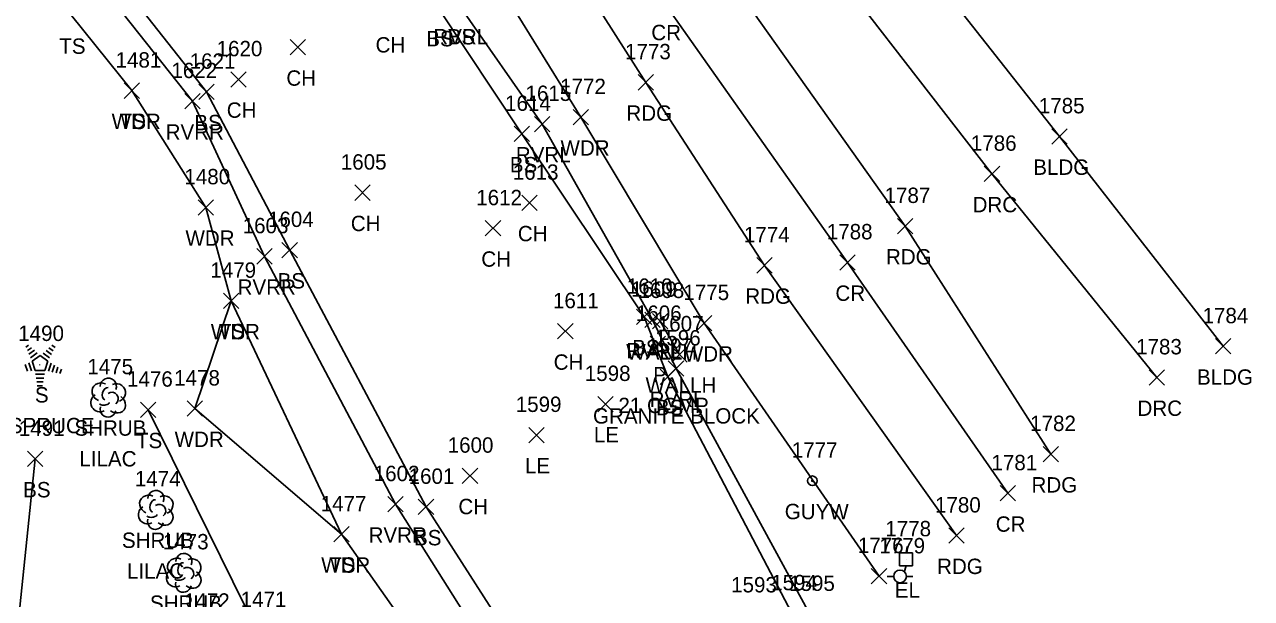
# Model space of a CAD drawing. Extents: x 1653908 to 1654393, y 539913 to 544256.
# Drawn here: x 1654097.1 to 1654256.7, y 541473.4 to 541548 of the extents above; entities that cross this region are included whole.
import ezdxf

# ---------------------------------------------------------------- set-up
doc = ezdxf.new("R2010")
doc.units = 0
for name, color, linetype in [('D_A', 7, 'Continuous'), ('D_C', 7, 'Continuous'), ('D_I', 7, 'Continuous'), ('D_TIC', 7, 'Continuous'), ('DHW', 7, 'Continuous'), ('L_A', 7, 'Continuous'), ('L_C', 7, 'Continuous'), ('L_I', 7, 'Continuous'), ('L_TIC', 7, 'Continuous'), ('LAWA', 7, 'Continuous'), ('LAWE', 7, 'Continuous'), ('LBC', 7, 'Continuous'), ('LELB', 7, 'Continuous'), ('LSH', 7, 'Continuous'), ('LTC', 7, 'Continuous'), ('P_A', 7, 'Continuous'), ('P_I', 7, 'Continuous'), ('P_TIC', 7, 'Continuous'), ('PEU', 7, 'Continuous'), ('PRC', 7, 'Continuous'), ('R_A', 7, 'Continuous'), ('R_I', 7, 'Continuous'), ('R_TIC', 7, 'Continuous'), ('RDP', 7, 'Continuous'), ('U_A', 7, 'Continuous'), ('U_I', 7, 'Continuous'), ('UEPT', 7, 'Continuous'), ('UP', 7, 'Continuous'), ('UPGW', 7, 'Continuous')]:
    doc.layers.add(name, color=color, linetype=linetype)

msp = doc.modelspace()

# ---------------------------------------------------------------- linework, layer by layer
at = {"layer": 'D_TIC'}
for points in [[(1654178.8, 541508.46), (1654180.8, 541510.46)], [(1654180.8, 541508.46), (1654178.8, 541510.46)], [(1654178.51, 541505.49), (1654180.51, 541507.49)], [(1654180.51, 541505.49), (1654178.51, 541507.49)], [(1654181.31, 541504.13), (1654183.31, 541506.13)], [(1654183.31, 541504.13), (1654181.31, 541506.13)]]:
    msp.add_lwpolyline(points, dxfattribs=at)
at = {"layer": 'DHW'}
msp.add_lwpolyline([(1654182.31, 541505.13), (1654179.8, 541509.46)], dxfattribs=at)
at = {"layer": 'L_TIC'}
for points in [[(1654131.7, 541544.07), (1654133.7, 541546.07)], [(1654133.7, 541544.07), (1654131.7, 541546.07)], [(1654123.95, 541539.9), (1654125.95, 541541.9)], [(1654125.95, 541539.9), (1654123.95, 541541.9)], [(1654110.1, 541538.43), (1654112.1, 541540.43)], [(1654112.1, 541538.43), (1654110.1, 541540.43)], [(1654110.1, 541538.43), (1654112.1, 541540.43)], [(1654112.1, 541538.43), (1654110.1, 541540.43)], [(1654119.79, 541538.28), (1654121.79, 541540.28)], [(1654121.79, 541538.28), (1654119.79, 541540.28)], [(1654117.98, 541537.06), (1654119.98, 541539.06)], [(1654119.98, 541537.06), (1654117.98, 541539.06)], [(1654163.46, 541534.09), (1654165.46, 541536.09)], [(1654165.46, 541534.09), (1654163.46, 541536.09)], [(1654168.48, 541534.98), (1654170.48, 541536.98)], [(1654170.48, 541534.98), (1654168.48, 541536.98)], [(1654160.8, 541532.8), (1654162.8, 541534.8)], [(1654162.8, 541532.8), (1654160.8, 541534.8)], [(1654230.73, 541532.48), (1654232.73, 541534.48)], [(1654232.73, 541532.48), (1654230.73, 541534.48)], [(1654140.09, 541525.16), (1654142.09, 541527.16)], [(1654142.09, 541525.16), (1654140.09, 541527.16)], [(1654119.71, 541523.25), (1654121.71, 541525.25)], [(1654121.71, 541523.25), (1654119.71, 541525.25)], [(1654161.8, 541523.84), (1654163.8, 541525.84)], [(1654163.8, 541523.84), (1654161.8, 541525.84)], [(1654157.06, 541520.53), (1654159.06, 541522.53)], [(1654159.06, 541520.53), (1654157.06, 541522.53)], [(1654130.62, 541517.7), (1654132.62, 541519.7)], [(1654132.62, 541517.7), (1654130.62, 541519.7)], [(1654127.33, 541516.88), (1654129.33, 541518.88)], [(1654129.33, 541516.88), (1654127.33, 541518.88)], [(1654123, 541511.09), (1654125, 541513.09)], [(1654125, 541511.09), (1654123, 541513.09)], [(1654123, 541511.09), (1654125, 541513.09)], [(1654125, 541511.09), (1654123, 541513.09)], [(1654176.72, 541509.01), (1654178.72, 541511.01)], [(1654178.72, 541509.01), (1654176.72, 541511.01)], [(1654177.82, 541508.62), (1654179.82, 541510.62)], [(1654179.82, 541508.62), (1654177.82, 541510.62)], [(1654184.51, 541508.19), (1654186.51, 541510.19)], [(1654186.51, 541508.19), (1654184.51, 541510.19)], [(1654166.47, 541507.13), (1654168.47, 541509.13)], [(1654168.47, 541507.13), (1654166.47, 541509.13)], [(1654252.02, 541505.18), (1654254.02, 541507.18)], [(1654254.02, 541505.18), (1654252.02, 541507.18)], [(1654180.86, 541502.28), (1654182.86, 541504.28)], [(1654182.86, 541502.28), (1654180.86, 541504.28)], [(1654179.81, 541501.22), (1654181.81, 541503.22)], [(1654181.81, 541501.22), (1654179.81, 541503.22)], [(1654112.22, 541496.93), (1654114.22, 541498.93)], [(1654114.22, 541496.93), (1654112.22, 541498.93)], [(1654118.3, 541497.08), (1654120.3, 541499.08)], [(1654120.3, 541497.08), (1654118.3, 541499.08)], [(1654171.69, 541497.67), (1654173.69, 541499.67)], [(1654173.69, 541497.67), (1654171.69, 541499.67)], [(1654162.72, 541493.64), (1654164.72, 541495.64)], [(1654164.72, 541493.64), (1654162.72, 541495.64)], [(1654097.52, 541490.53), (1654099.52, 541492.53)], [(1654099.52, 541490.53), (1654097.52, 541492.53)], [(1654154.07, 541488.34), (1654156.07, 541490.34)], [(1654156.07, 541488.34), (1654154.07, 541490.34)], [(1654144.37, 541484.64), (1654146.37, 541486.64)], [(1654146.37, 541484.64), (1654144.37, 541486.64)], [(1654148.35, 541484.29), (1654150.35, 541486.29)], [(1654150.35, 541484.29), (1654148.35, 541486.29)], [(1654137.36, 541480.73), (1654139.36, 541482.73)], [(1654139.36, 541480.73), (1654137.36, 541482.73)], [(1654137.36, 541480.73), (1654139.36, 541482.73)], [(1654139.36, 541480.73), (1654137.36, 541482.73)], [(1654207.26, 541475.29), (1654209.26, 541477.29)], [(1654209.26, 541475.29), (1654207.26, 541477.29)]]:
    msp.add_lwpolyline(points, dxfattribs=at)
at = {"layer": 'LAWA'}
for points in [[(1654127.87, 541598.37), (1654149.12, 541568.97), (1654169.48, 541535.98), (1654185.51, 541509.19), (1654208.26, 541476.29)], [(1654160.84, 541449.79), (1654138.36, 541481.73), (1654119.3, 541498.08), (1654124, 541512.09), (1654120.71, 541524.25), (1654111.1, 541539.43)]]:
    msp.add_lwpolyline(points, dxfattribs=at)
at = {"layer": 'LAWE'}
for points in [[(1654199.26, 541471.36), (1654181.86, 541503.28), (1654178.82, 541509.62), (1654164.46, 541535.09), (1654153.73, 541550.44), (1654126.86, 541584.5), (1654110.11, 541605.8), (1654090.45, 541629.39), (1654082.44, 541647.34), (1654069.57, 541661.67), (1654051.08, 541684.15), (1654038.47, 541696.15), (1654026.73, 541704.45), (1654010.8, 541724.45), (1653979.68, 541745.5), (1653961.84, 541751.35), (1653943.48, 541769.15)], [(1654165.75, 541453.3), (1654145.37, 541485.64), (1654128.33, 541517.88), (1654118.98, 541538.06), (1654102.88, 541558.43), (1654087.64, 541571.29), (1654080.69, 541574.23), (1654068.7, 541590.65), (1654047.98, 541616.51), (1654043.58, 541623.07), (1654031.27, 541642.94), (1654001.65, 541675.05), (1653981.82, 541702.27), (1653972.91, 541712.11), (1653946.21, 541722.65), (1653929.33, 541730.47)]]:
    msp.add_lwpolyline(points, dxfattribs=at)
at = {"layer": 'LBC'}
msp.add_lwpolyline([(1654253.02, 541506.18), (1654231.73, 541533.48), (1654203.1, 541569.78), (1654212.42, 541577.2)], dxfattribs=at)
at = {"layer": 'LELB'}
for points in [[(1654196.93, 541471.45), (1654180.81, 541502.22), (1654177.72, 541510.01), (1654161.8, 541533.8), (1654150.94, 541550.19), (1654125.25, 541583.39), (1654108.34, 541603.18), (1654088.22, 541626.26), (1654081.33, 541637.75)], [(1654167.93, 541456.34), (1654149.35, 541485.29), (1654131.62, 541518.7), (1654120.79, 541539.28), (1654104.43, 541560.1), (1654087.96, 541576.78)], [(1654111.1, 541539.43), (1654103.25, 541549.22), (1654091.64, 541558.03), (1654091.64, 541546.03), (1654092.66, 541531.19), (1654087.6, 541525.06), (1654080.77, 541525.51), (1654079.92, 541532.39), (1654080.83, 541544.02)], [(1654138.36, 541481.73), (1654124, 541512.09)], [(1654160.84, 541449.79), (1654142.77, 541456.54), (1654127.36, 541469.26), (1654113.22, 541497.93)], [(1654131.27, 541408.59), (1654106.78, 541414.13), (1654086.76, 541412.9), (1654094.61, 541453.8), (1654098.52, 541491.53)]]:
    msp.add_lwpolyline(points, dxfattribs=at)
at = {"layer": 'LSH'}
for p, q in [((1654108, 541499.55), (1654108, 541499.55)), ((1654108, 541499.55), (1654108, 541499.55)), ((1654114.18, 541484.96), (1654114.18, 541484.96)), ((1654114.18, 541484.96), (1654114.18, 541484.96)), ((1654117.82, 541476.77), (1654117.82, 541476.77)), ((1654117.82, 541476.77), (1654117.82, 541476.77))]:
    msp.add_line(p, q, dxfattribs=at)
for centre in [(1654108.04, 541500.99), (1654114.23, 541486.39), (1654117.87, 541478.2)]:
    msp.add_arc(centre, 1.05, 335.5272, 180.9563, dxfattribs=at)
for centre, major_axis, ratio, start_param, end_param in [((1654107.21, 541500.22), (1.21, -0.51), 0.895232, 1.570796, 4.712389), ((1654107.79, 541500.01), (-0.208, -0.792), 0.645439, 3.141593, 6.283185), ((1654109.04, 541500.13), (-1.14, -0.48), 0.949671, 1.570796, 4.712389), ((1654106.91, 541498.84), (0.58, -1.04), 0.959034, 3.141593, 6.283185), ((1654107.54, 541498.8), (-0.625, -0.083), 0.423636, 0, 3.141593), ((1654108.5, 541499.38), (-0.5, 0.667), 0.989748, 3.141593, 6.283185), ((1654109, 541498.72), (-1.09, 0.79), 0.841452, 1.570796, 4.712389), ((1654108, 541498.05), (0.26, 1.06), 0.942809, 1.570796, 4.712389), ((1654113.39, 541485.62), (1.21, -0.51), 0.895232, 1.570796, 4.712389), ((1654113.98, 541485.42), (-0.208, -0.792), 0.645439, 3.141593, 6.283185), ((1654115.23, 541485.54), (-1.14, -0.48), 0.949671, 1.570796, 4.712389), ((1654113.1, 541484.25), (0.58, -1.04), 0.959034, 3.141593, 6.283185), ((1654114.68, 541484.79), (-0.5, 0.667), 0.989748, 3.141593, 6.283185), ((1654115.18, 541484.12), (-1.09, 0.79), 0.841452, 1.570796, 4.712389), ((1654114.18, 541483.46), (0.26, 1.06), 0.942809, 1.570796, 4.712389), ((1654113.73, 541484.21), (-0.625, -0.083), 0.423636, 0, 3.141593), ((1654117.03, 541477.43), (1.21, -0.51), 0.895232, 1.570796, 4.712389), ((1654117.61, 541477.22), (-0.208, -0.792), 0.645439, 3.141593, 6.283185), ((1654118.86, 541477.35), (-1.14, -0.48), 0.949671, 1.570796, 4.712389), ((1654116.74, 541476.06), (0.58, -1.04), 0.959034, 3.141593, 6.283185), ((1654118.32, 541476.6), (-0.5, 0.667), 0.989748, 3.141593, 6.283185), ((1654118.82, 541475.93), (-1.09, 0.79), 0.841452, 1.570796, 4.712389), ((1654117.82, 541475.27), (0.26, 1.06), 0.942809, 1.570796, 4.712389), ((1654117.36, 541476.02), (-0.625, -0.083), 0.423636, 0, 3.141593)]:
    msp.add_ellipse(centre, major_axis=major_axis, ratio=ratio, start_param=start_param, end_param=end_param, dxfattribs=at)
at = {"layer": 'LTC'}
for p, q in [((1654097.3, 541506.08), (1654097.65, 541506.34)), ((1654097.51, 541505.62), (1654098.04, 541506)), ((1654097.72, 541505.15), (1654098.42, 541505.66)), ((1654097.93, 541504.69), (1654098.8, 541505.32)), ((1654099.58, 541505.28), (1654100.39, 541504.69)), ((1654099.95, 541505.63), (1654100.63, 541505.13)), ((1654100.32, 541505.97), (1654100.87, 541505.58)), ((1654100.69, 541506.32), (1654101.11, 541506.02)), ((1654097.24, 541503.8), (1654097.51, 541502.96)), ((1654097.7, 541504.01), (1654098.03, 541502.99)), ((1654098.15, 541504.23), (1654099.16, 541504.97)), ((1654098.15, 541504.23), (1654098.54, 541503.04)), ((1654099.16, 541504.97), (1654100.16, 541504.24)), ((1654100.16, 541504.24), (1654099.77, 541503.04)), ((1654100.6, 541503.97), (1654100.26, 541502.93)), ((1654101.04, 541503.72), (1654100.75, 541502.83)), ((1654099.77, 541503.04), (1654098.54, 541503.04)), ((1654099.73, 541502.54), (1654098.58, 541502.54)), ((1654099.65, 541502.04), (1654098.66, 541502.04)), ((1654101.49, 541503.47), (1654101.25, 541502.74)), ((1654101.93, 541503.22), (1654101.74, 541502.64)), ((1654099.56, 541501.54), (1654098.73, 541501.54)), ((1654099.48, 541501.04), (1654098.8, 541501.04))]:
    msp.add_line(p, q, dxfattribs=at)
at = {"layer": 'P_TIC'}
for points in [[(1654176.92, 541539.51), (1654178.92, 541541.51)], [(1654178.92, 541539.51), (1654176.92, 541541.51)], [(1654210.67, 541520.82), (1654212.67, 541522.82)], [(1654212.67, 541520.82), (1654210.67, 541522.82)], [(1654203.16, 541516.09), (1654205.16, 541518.09)], [(1654205.16, 541516.09), (1654203.16, 541518.09)], [(1654192.38, 541515.71), (1654194.38, 541517.71)], [(1654194.38, 541515.71), (1654192.38, 541517.71)], [(1654229.6, 541491.16), (1654231.6, 541493.16)], [(1654231.6, 541491.16), (1654229.6, 541493.16)], [(1654224.01, 541486.06), (1654226.01, 541488.06)], [(1654226.01, 541486.06), (1654224.01, 541488.06)], [(1654217.32, 541480.56), (1654219.32, 541482.56)], [(1654219.32, 541480.56), (1654217.32, 541482.56)]]:
    msp.add_lwpolyline(points, dxfattribs=at)
at = {"layer": 'PEU'}
for points in [[(1654230.6, 541492.16), (1654211.67, 541521.82), (1654186.95, 541556.68), (1654161.81, 541592.26), (1654146.11, 541619.61), (1654138.24, 541633.78), (1654124.52, 541663.98), (1654122.03, 541667.7)], [(1654099.96, 541660.14), (1654114.2, 541641.31), (1654138.77, 541602.77), (1654156.2, 541574.57), (1654177.92, 541540.51), (1654193.38, 541516.71), (1654218.32, 541481.56)]]:
    msp.add_lwpolyline(points, dxfattribs=at)
at = {"layer": 'PRC'}
msp.add_lwpolyline([(1654225.01, 541487.06), (1654204.16, 541517.09), (1654180.22, 541550.99), (1654156.18, 541588.24), (1654139.45, 541615.76), (1654117.3, 541653.68), (1654111.9, 541663.59), (1654098.63, 541686.77), (1654084.43, 541705.04)], dxfattribs=at)
at = {"layer": 'R_TIC'}
for points in [[(1654221.95, 541527.61), (1654223.95, 541529.61)], [(1654223.95, 541527.61), (1654221.95, 541529.61)], [(1654243.38, 541501.13), (1654245.38, 541503.13)], [(1654245.38, 541501.13), (1654243.38, 541503.13)]]:
    msp.add_lwpolyline(points, dxfattribs=at)
at = {"layer": 'RDP'}
msp.add_lwpolyline([(1654244.38, 541502.13), (1654222.95, 541528.61), (1654195.82, 541563.61), (1654203.1, 541569.78)], dxfattribs=at)
at = {"layer": 'UEPT'}
for p, q in [((1654211.94, 541480.14), (1654211.77, 541479.31)), ((1654210.94, 541477.64), (1654210.94, 541479.31)), ((1654210.94, 541479.31), (1654212.61, 541479.31)), ((1654211.77, 541478.47), (1654211.77, 541478.47)), ((1654212.61, 541479.31), (1654212.61, 541477.64)), ((1654212.61, 541477.64), (1654210.94, 541477.64)), ((1654211.52, 541476.81), (1654211.77, 541477.64))]:
    msp.add_line(p, q, dxfattribs=at)
at = {"layer": 'UP'}
for p, q in [((1654209.34, 541476.24), (1654210.17, 541476.24)), ((1654211, 541476.25), (1654211, 541476.25)), ((1654212.67, 541476.25), (1654211.83, 541476.25)), ((1654211.83, 541476.25), (1654211.83, 541476.25)), ((1654212.67, 541476.25), (1654212.67, 541476.25))]:
    msp.add_line(p, q, dxfattribs=at)
msp.add_circle((1654211, 541476.25), 0.833, dxfattribs=at)
at = {"layer": 'UPGW'}
for radius in [0.625, 0.0833]:
    msp.add_circle((1654199.6, 541488.69), radius, dxfattribs=at)

# ---------------------------------------------------------------- texts
at = {"layer": 'D_A'}
for s, p in [('WALLH', (1654175.39, 541504.46)), ('WALLH', (1654177.9, 541500.13)), ('P', (1654178.89, 541501.49))]:
    msp.add_text(s, height=2, dxfattribs=at).set_placement(p)
at = {"layer": 'D_C'}
for s, p in [('21 CGMP', (1654174.37, 541497.49)), ('GRANITE BLOCK', (1654171.07, 541496.13))]:
    msp.add_text(s, height=2, dxfattribs=at).set_placement(p)
at = {"layer": 'D_I'}
for s, p in [('1608', (1654176.98, 541512.46)), ('1606', (1654176.64, 541509.49)), ('1607', (1654179.49, 541508.13))]:
    msp.add_text(s, height=2, dxfattribs=at).set_placement(p)
at = {"layer": 'L_A'}
for s, p in [('BS', (1654149.38, 541545.19)), ('RVRL', (1654150.3, 541545.44)), ('BS', (1654152.17, 541545.44)), ('TS', (1654101.66, 541544.22)), ('CH', (1654142.79, 541544.39)), ('CH', (1654131.19, 541540.07)), ('CH', (1654123.44, 541535.9)), ('WDR', (1654108.47, 541534.43)), ('TS', (1654109.51, 541534.43)), ('BS', (1654119.23, 541534.28)), ('RVRR', (1654115.49, 541533.06)), ('WDR', (1654166.84, 541530.98)), ('BS', (1654160.25, 541528.8)), ('RVRL', (1654161.03, 541530.09)), ('BLDG', (1654228.32, 541528.48)), ('CH', (1654139.57, 541521.16)), ('WDR', (1654118.07, 541519.25)), ('CH', (1654161.29, 541519.84)), ('CH', (1654156.54, 541516.53)), ('RVRR', (1654124.85, 541512.88)), ('BS', (1654130.06, 541513.7)), ('WDR', (1654121.36, 541507.09)), ('TS', (1654122.41, 541507.09)), ('BS', (1654176.16, 541505.01)), ('CH', (1654165.95, 541503.13)), ('RVRL', (1654175.39, 541504.62)), ('WDR', (1654182.88, 541504.19)), ('BLDG', (1654249.61, 541501.18)), ('S', (1654098.49, 541498.87)), ('RVRL', (1654178.43, 541498.28)), ('BS', (1654179.25, 541497.22)), ('SHRUB', (1654103.63, 541494.55)), ('LE', (1654171.18, 541493.67)), ('TS', (1654111.63, 541492.93)), ('WDR', (1654116.66, 541493.08)), ('LE', (1654162.21, 541489.64)), ('BS', (1654096.96, 541486.53)), ('CH', (1654153.56, 541484.34)), ('SHRUB', (1654109.81, 541479.96)), ('RVRR', (1654141.88, 541480.64)), ('BS', (1654147.79, 541480.29)), ('WDR', (1654135.72, 541476.73)), ('TS', (1654136.76, 541476.73)), ('SHRUB', (1654113.45, 541471.77))]:
    msp.add_text(s, height=2, dxfattribs=at).set_placement(p)
at = {"layer": 'L_C'}
for s, p in [('S. SPRUCE', (1654091.83, 541494.87)), ('LILAC', (1654104.27, 541490.55)), ('LILAC', (1654110.46, 541475.96))]:
    msp.add_text(s, height=2, dxfattribs=at).set_placement(p)
at = {"layer": 'L_I'}
for s, p in [('1620', (1654122.12, 541543.9)), ('1481', (1654108.98, 541542.43)), ('1481', (1654108.98, 541542.43)), ('1621', (1654118.62, 541542.28)), ('1622', (1654116.24, 541541.06)), ('1772', (1654166.79, 541538.98)), ('1614', (1654159.63, 541536.8)), ('1615', (1654162.29, 541538.09)), ('1785', (1654229.04, 541536.48)), ('1605', (1654138.27, 541529.16)), ('1480', (1654117.93, 541527.25)), ('1613', (1654160.63, 541527.84)), ('1612', (1654155.88, 541524.53)), ('1603', (1654125.51, 541520.88)), ('1604', (1654128.8, 541521.7)), ('1479', (1654121.3, 541515.09)), ('1479', (1654121.3, 541515.09)), ('1610', (1654175.46, 541513.01)), ('1611', (1654165.86, 541511.13)), ('1609', (1654176, 541512.62)), ('1775', (1654182.82, 541512.19)), ('1784', (1654250.33, 541509.18)), ('1490', (1654096.32, 541506.87)), ('1597', (1654178.12, 541505.22)), ('1596', (1654179.12, 541506.28)), ('1475', (1654105.31, 541502.55)), ('1598', (1654170, 541501.67)), ('1476', (1654110.47, 541500.93)), ('1478', (1654116.6, 541501.08)), ('1599', (1654161.02, 541497.64)), ('1491', (1654096.39, 541494.53)), ('1600', (1654152.17, 541492.34)), ('1474', (1654111.49, 541487.96)), ('1602', (1654142.55, 541488.64)), ('1601', (1654147.09, 541488.29)), ('1477', (1654135.66, 541484.73)), ('1477', (1654135.66, 541484.73)), ('1473', (1654115.13, 541479.77)), ('1776', (1654205.51, 541479.29)), ('1594', (1654194.24, 541474.45)), ('1593', (1654189.03, 541474.17)), ('1595', (1654196.57, 541474.36)), ('1472', (1654117.87, 541472.05)), ('1471', (1654125.24, 541472.26))]:
    msp.add_text(s, height=2, dxfattribs=at).set_placement(p)
at = {"layer": 'LTC'}
msp.add_text('.', height=1.04, rotation=270, dxfattribs=at).set_placement((1654099.04, 541503.98))
at = {"layer": 'P_A'}
for s, p in [('CR', (1654178.65, 541545.99)), ('RDG', (1654175.41, 541535.51)), ('RDG', (1654209.16, 541516.82)), ('RDG', (1654190.87, 541511.71)), ('CR', (1654202.59, 541512.09)), ('RDG', (1654228.09, 541487.16)), ('CR', (1654223.44, 541482.06)), ('RDG', (1654215.81, 541476.56))]:
    msp.add_text(s, height=2, dxfattribs=at).set_placement(p)
at = {"layer": 'P_I'}
for s, p in [('1773', (1654175.23, 541543.51)), ('1787', (1654208.98, 541524.82)), ('1774', (1654190.69, 541519.71)), ('1788', (1654201.47, 541520.09)), ('1782', (1654227.91, 541495.16)), ('1781', (1654222.88, 541490.06)), ('1780', (1654215.54, 541484.56))]:
    msp.add_text(s, height=2, dxfattribs=at).set_placement(p)
at = {"layer": 'R_A'}
for p in [(1654220.43, 541523.61), (1654241.87, 541497.13)]:
    msp.add_text('DRC', height=2, dxfattribs=at).set_placement(p)
at = {"layer": 'R_I'}
for s, p in [('1786', (1654220.2, 541531.61)), ('1783', (1654241.69, 541505.13))]:
    msp.add_text(s, height=2, dxfattribs=at).set_placement(p)
at = {"layer": 'U_A'}
for s, p in [('GUYW', (1654196, 541483.69)), ('EL', (1654210.31, 541473.47))]:
    msp.add_text(s, height=2, dxfattribs=at).set_placement(p)
at = {"layer": 'U_I'}
for s, p in [('1777', (1654196.91, 541491.69)), ('1778', (1654209.08, 541481.47)), ('1779', (1654208.3, 541479.25))]:
    msp.add_text(s, height=2, dxfattribs=at).set_placement(p)

doc.saveas('drawing.dxf')
